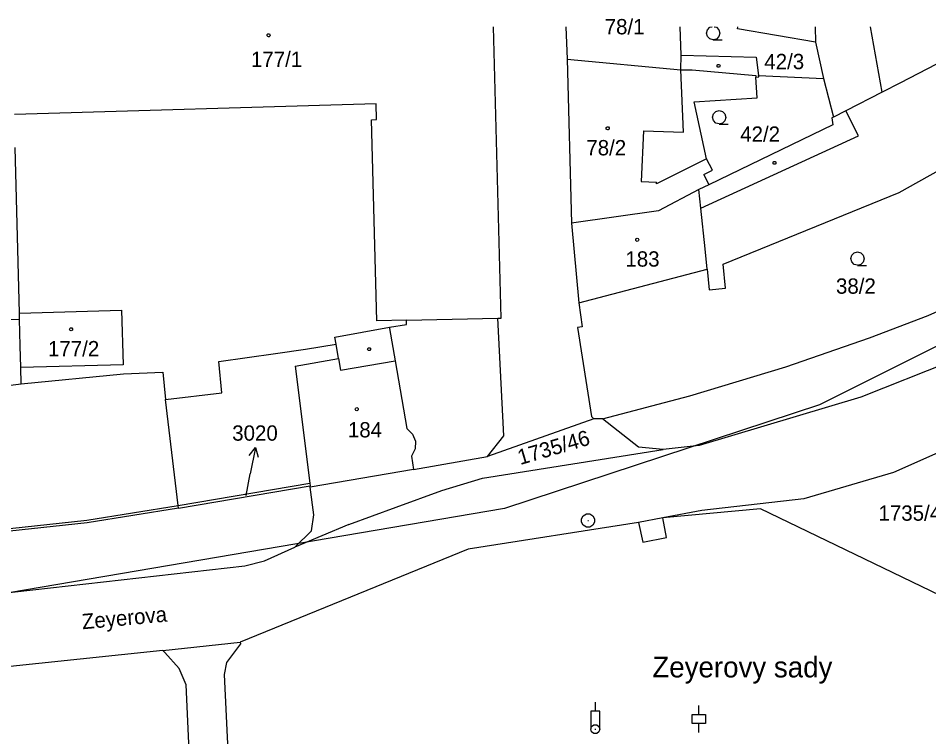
# Model space of a CAD drawing. Extents: x -777309 to -774195, y -1144706 to -1143600.
# Drawn here: x -774798.5 to -774697.4, y -1144278.9 to -1144199.1 of the extents above; entities that cross this region are included whole.
import ezdxf

# ---------------------------------------------------------------- set-up
doc = ezdxf.new("R2010")
doc.units = 0
for name, color, linetype in [('1', 7, 'Continuous'), ('11', 7, 'Continuous'), ('12', 7, 'Continuous'), ('2', 7, 'Continuous'), ('3', 7, 'Continuous'), ('4', 7, 'Continuous'), ('5', 7, 'Continuous'), ('6', 7, 'Continuous'), ('7', 7, 'Continuous'), ('8', 7, 'Continuous')]:
    doc.layers.add(name, color=color, linetype=linetype)

msp = doc.modelspace()

# ---------------------------------------------------------------- linework, layer by layer
at = {"layer": '1'}
for p, q in [((-774744.88, -1144232.39), (-774745.71, -1144200)), ((-774737.67, -1144200), (-774737.55, -1144203.61)), ((-774724.88, -1144203.17), (-774724.98, -1144200)), ((-774718.61, -1144200.24), (-774718.57, -1144200)), ((-774709.96, -1144201.73), (-774718.61, -1144200.24)), ((-774709.99, -1144200), (-774709.96, -1144201.73)), ((-774709.96, -1144201.73), (-774709.07, -1144205.77)), ((-774737.55, -1144203.61), (-774737.05, -1144221.81)), ((-774737.55, -1144203.61), (-774724.92, -1144204.81)), ((-774724.88, -1144203.17), (-774716.53, -1144203.38)), ((-774716.53, -1144203.38), (-774716.27, -1144205.42)), ((-774724.92, -1144204.81), (-774723.65, -1144204.81)), ((-774723.65, -1144204.81), (-774716.59, -1144205.44)), ((-774696.6, -1144204.21), (-774700.52, -1144206.23)), ((-774716.59, -1144205.44), (-774716.58, -1144205.6)), ((-774716.58, -1144205.6), (-774716.26, -1144205.56)), ((-774716.44, -1144207.9), (-774716.58, -1144205.6)), ((-774716.26, -1144205.56), (-774716.27, -1144205.42)), ((-774716.27, -1144205.42), (-774709.07, -1144205.77)), ((-774709.07, -1144205.77), (-774707.96, -1144210.06)), ((-774700.52, -1144206.23), (-774702.57, -1144207.28)), ((-774723.44, -1144208.33), (-774716.44, -1144207.9)), ((-774702.57, -1144207.28), (-774706.6, -1144209.36)), ((-774722.05, -1144214.66), (-774723.44, -1144208.33)), ((-774706.6, -1144209.36), (-774707.96, -1144210.06)), ((-774708.05, -1144210.89), (-774721.82, -1144217.55)), ((-774707.96, -1144210.06), (-774708.15, -1144210.11)), ((-774708.15, -1144210.11), (-774708.05, -1144210.89)), ((-774700.67, -1144218.43), (-774689.32, -1144212.02)), ((-774798.37, -1144231.8), (-774798.85, -1144213.42)), ((-774721.4, -1144215.93), (-774722.05, -1144214.66)), ((-774722.37, -1144216.41), (-774721.4, -1144215.93)), ((-774722.37, -1144216.41), (-774721.82, -1144217.55)), ((-774722.91, -1144218.07), (-774727.41, -1144220.45)), ((-774721.82, -1144217.55), (-774722.91, -1144218.07)), ((-774720.23, -1144226.39), (-774700.67, -1144218.43)), ((-774727.41, -1144220.45), (-774737.05, -1144221.81)), ((-774737.05, -1144221.81), (-774736.23, -1144230.66)), ((-774736.23, -1144230.66), (-774721.99, -1144226.92)), ((-774721.99, -1144226.92), (-774721.75, -1144229.22)), ((-774719.95, -1144229.04), (-774720.23, -1144226.39)), ((-774721.75, -1144229.22), (-774719.95, -1144229.04)), ((-774697.45, -1144232.07), (-774692.97, -1144230.06)), ((-774736.23, -1144230.66), (-774735.86, -1144233.33)), ((-774798.37, -1144231.8), (-774787.02, -1144231.5)), ((-774798.36, -1144232.49), (-774798.37, -1144231.8)), ((-774787.02, -1144231.5), (-774786.86, -1144237.57)), ((-774703.97, -1144234.55), (-774697.45, -1144232.07)), ((-774798.28, -1144235.46), (-774798.36, -1144232.49)), ((-774757.29, -1144233.37), (-774755.38, -1144233.06)), ((-774755.39, -1144232.61), (-774745.25, -1144232.39)), ((-774755.38, -1144233.06), (-774755.39, -1144232.61)), ((-774744.56, -1144245.45), (-774745.25, -1144232.39)), ((-774745.25, -1144232.39), (-774744.88, -1144232.39)), ((-774763.34, -1144234.5), (-774757.29, -1144233.37)), ((-774735.86, -1144233.33), (-774736.39, -1144233.4)), ((-774736.39, -1144233.4), (-774734.85, -1144243.28)), ((-774766.6, -1144235.81), (-774763.21, -1144235.27)), ((-774763.21, -1144235.27), (-774763.34, -1144234.5)), ((-774713.26, -1144237.77), (-774703.97, -1144234.55)), ((-774798.22, -1144237.87), (-774798.28, -1144235.46)), ((-774776.23, -1144237.2), (-774769.93, -1144236.29)), ((-774769.93, -1144236.29), (-774766.6, -1144235.81)), ((-774775.88, -1144240.67), (-774776.23, -1144237.2)), ((-774694.36, -1144236.94), (-774704.94, -1144241.15)), ((-774786.86, -1144237.57), (-774798.22, -1144237.87)), ((-774798.17, -1144239.67), (-774798.22, -1144237.87)), ((-774723.9, -1144240.98), (-774713.26, -1144237.77)), ((-774798.17, -1144239.67), (-774786.83, -1144238.57)), ((-774786.83, -1144238.57), (-774782.45, -1144238.36)), ((-774782.45, -1144238.36), (-774782.14, -1144241.4)), ((-774808.13, -1144240.85), (-774798.17, -1144239.67)), ((-774782.14, -1144241.4), (-774775.88, -1144240.67)), ((-774733.62, -1144243.55), (-774723.9, -1144240.98)), ((-774704.94, -1144241.15), (-774722.87, -1144246.5)), ((-774780.75, -1144253.18), (-774782.14, -1144241.4)), ((-774734.85, -1144243.28), (-774734.58, -1144243.54)), ((-774734.58, -1144243.54), (-774746.39, -1144247.74)), ((-774733.62, -1144243.55), (-774734.58, -1144243.54)), ((-774729.62, -1144246.7), (-774733.62, -1144243.55)), ((-774690.18, -1144244.53), (-774701.28, -1144249.52)), ((-774746.39, -1144247.74), (-774744.56, -1144245.45)), ((-774746.93, -1144250.16), (-774726.89, -1144246.95)), ((-774726.89, -1144246.95), (-774729.62, -1144246.7)), ((-774722.87, -1144246.5), (-774726.89, -1144246.95)), ((-774754.59, -1144249.19), (-774746.39, -1144247.74)), ((-774754.59, -1144249.19), (-774766.07, -1144251.14)), ((-774751.47, -1144251.53), (-774746.93, -1144250.16)), ((-774701.28, -1144249.52), (-774711.26, -1144252.45)), ((-774780.75, -1144253.18), (-774766.11, -1144250.71)), ((-774780.72, -1144253.48), (-774766.07, -1144251.01)), ((-774766.11, -1144250.71), (-774766.07, -1144251.01)), ((-774766.07, -1144251.14), (-774766.07, -1144251.01)), ((-774765.68, -1144254.21), (-774766.07, -1144251.14)), ((-774756.55, -1144253.36), (-774751.47, -1144251.53)), ((-774711.26, -1144252.45), (-774722.58, -1144253.73)), ((-774790.9, -1144254.82), (-774780.75, -1144253.18)), ((-774780.72, -1144253.48), (-774790.85, -1144255.12)), ((-774780.72, -1144253.48), (-774780.75, -1144253.18)), ((-774761.79, -1144255.3), (-774756.55, -1144253.36)), ((-774765.94, -1144256.01), (-774765.68, -1144254.21)), ((-774716.05, -1144253.53), (-774726.9, -1144254.54)), ((-774722.58, -1144253.73), (-774726.9, -1144254.54)), ((-774668.54, -1144276.54), (-774716.05, -1144253.53)), ((-774809.2, -1144256.75), (-774790.9, -1144254.82)), ((-774790.85, -1144255.12), (-774809.17, -1144257.05)), ((-774761.79, -1144255.3), (-774767.79, -1144257.79)), ((-774729.6, -1144255.07), (-774748.54, -1144258.04)), ((-774726.9, -1144254.54), (-774729.6, -1144255.07)), ((-774767.79, -1144257.79), (-774765.94, -1144256.01)), ((-774748.54, -1144258.04), (-774773.87, -1144268.37)), ((-774771.17, -1144259.33), (-774767.79, -1144257.79)), ((-774773.33, -1144259.89), (-774771.17, -1144259.33)), ((-774818.72, -1144265.01), (-774773.33, -1144259.89)), ((-774782.45, -1144269.27), (-774773.87, -1144268.37)), ((-774773.83, -1144268.54), (-774775.39, -1144270.6)), ((-774773.87, -1144268.37), (-774773.83, -1144268.54)), ((-774782.45, -1144269.27), (-774818.84, -1144273.07)), ((-774775.39, -1144270.6), (-774775.64, -1144271.95)), ((-774775.64, -1144271.95), (-774774.8, -1144288.74))]:
    msp.add_line(p, q, dxfattribs=at)
at = {"layer": '11'}
msp.add_lwpolyline([(-774645.08, -1144200), (-774645.5, -1144200.5), (-774681.5, -1144228), (-774709.5, -1144242), (-774744.5, -1144253.5), (-774812, -1144265), (-774860.5, -1144263), (-774969.04, -1144252.1), (-774980.31, -1144239.8), (-774996.3, -1144228.96), (-775000, -1144226.45), (-775000, -1144224.76), (-775020.31, -1144224.68)], dxfattribs=at)
at = {"layer": '12'}
for p, q in [((-774744.88, -1144232.39), (-774745.71, -1144200)), ((-774737.67, -1144200), (-774737.55, -1144203.61)), ((-774724.88, -1144203.17), (-774724.98, -1144200)), ((-774737.55, -1144203.61), (-774724.92, -1144204.81)), ((-774737.55, -1144203.61), (-774737.05, -1144221.81)), ((-774737.55, -1144203.61), (-774724.92, -1144204.81)), ((-774724.92, -1144204.81), (-774724.88, -1144203.17)), ((-774724.62, -1144211.72), (-774724.92, -1144204.81)), ((-774758.75, -1144208.58), (-774798.94, -1144209.74)), ((-774758.7, -1144210.32), (-774758.75, -1144208.58)), ((-774759.27, -1144210.33), (-774758.7, -1144210.32)), ((-774758.67, -1144232.68), (-774759.27, -1144210.33)), ((-774729.06, -1144211.58), (-774729.33, -1144217.2)), ((-774729.06, -1144211.58), (-774724.62, -1144211.72)), ((-774722.05, -1144214.66), (-774727.6, -1144217.47)), ((-774721.4, -1144215.93), (-774722.05, -1144214.66)), ((-774722.37, -1144216.41), (-774721.4, -1144215.93)), ((-774722.37, -1144216.41), (-774721.82, -1144217.55)), ((-774729.33, -1144217.2), (-774727.61, -1144217.28)), ((-774727.6, -1144217.47), (-774727.61, -1144217.28)), ((-774722.91, -1144218.07), (-774727.41, -1144220.45)), ((-774722.91, -1144218.07), (-774727.41, -1144220.45)), ((-774721.82, -1144217.55), (-774722.91, -1144218.07)), ((-774722.69, -1144220.17), (-774722.91, -1144218.07)), ((-774727.41, -1144220.45), (-774737.05, -1144221.81)), ((-774727.41, -1144220.45), (-774737.05, -1144221.81)), ((-774722.23, -1144224.67), (-774722.69, -1144220.17)), ((-774737.05, -1144221.81), (-774736.23, -1144230.66)), ((-774721.99, -1144226.92), (-774722.23, -1144224.67)), ((-774736.23, -1144230.66), (-774721.99, -1144226.92)), ((-774798.37, -1144231.8), (-774787.02, -1144231.5)), ((-774798.36, -1144232.49), (-774798.37, -1144231.8)), ((-774787.02, -1144231.5), (-774786.86, -1144237.57)), ((-774798.28, -1144235.46), (-774798.36, -1144232.49)), ((-774755.39, -1144232.61), (-774758.67, -1144232.68)), ((-774755.39, -1144232.61), (-774745.25, -1144232.39)), ((-774745.25, -1144232.39), (-774744.88, -1144232.39)), ((-774798.22, -1144237.87), (-774798.28, -1144235.46)), ((-774767.74, -1144237.72), (-774762.93, -1144236.84)), ((-774762.93, -1144236.84), (-774762.7, -1144238.13)), ((-774762.7, -1144238.13), (-774756.65, -1144237.1)), ((-774756.65, -1144237.1), (-774755.36, -1144244.64)), ((-774786.86, -1144237.57), (-774798.22, -1144237.87)), ((-774767.74, -1144237.72), (-774766.11, -1144250.71)), ((-774755.36, -1144244.64), (-774754.7, -1144245.25)), ((-774754.7, -1144245.25), (-774754.38, -1144246.04)), ((-774754.38, -1144246.04), (-774754.41, -1144246.88)), ((-774754.41, -1144246.88), (-774754.84, -1144247.69)), ((-774754.84, -1144247.69), (-774754.59, -1144249.19)), ((-774754.59, -1144249.19), (-774766.07, -1144251.14)), ((-774766.11, -1144250.71), (-774766.07, -1144251.01)), ((-774766.07, -1144251.14), (-774766.07, -1144251.01))]:
    msp.add_line(p, q, dxfattribs=at)
at = {"layer": '3'}
msp.add_line((-774722.91, -1144276.38), (-774722.91, -1144275.38), dxfattribs=at)
for points in [[(-774721.31, -1144201.45), (-774721.69, -1144201.35), (-774721.96, -1144201.08), (-774722.06, -1144200.71), (-774721.96, -1144200.34), (-774721.69, -1144200.07), (-774721.43, -1144200)], [(-774721.21, -1144200), (-774720.95, -1144200.07), (-774720.68, -1144200.34), (-774720.58, -1144200.72), (-774720.68, -1144201.1), (-774720.95, -1144201.37), (-774721.33, -1144201.47), (-774720.33, -1144201.47)], [(-774720.64, -1144210.8), (-774721.02, -1144210.7), (-774721.29, -1144210.43), (-774721.39, -1144210.06), (-774721.29, -1144209.69), (-774721.02, -1144209.42), (-774720.65, -1144209.32), (-774720.28, -1144209.42), (-774720.01, -1144209.69), (-774719.91, -1144210.07), (-774720.01, -1144210.45), (-774720.28, -1144210.72), (-774720.66, -1144210.82), (-774719.66, -1144210.82)], [(-774705.28, -1144226.5), (-774705.66, -1144226.4), (-774705.93, -1144226.13), (-774706.03, -1144225.76), (-774705.93, -1144225.39), (-774705.66, -1144225.12), (-774705.29, -1144225.02), (-774704.92, -1144225.12), (-774704.65, -1144225.39), (-774704.55, -1144225.77), (-774704.65, -1144226.15), (-774704.92, -1144226.42), (-774705.3, -1144226.52), (-774704.3, -1144226.52)], [(-774722.91, -1144278.38), (-774722.91, -1144277.38), (-774723.66, -1144277.38), (-774723.66, -1144276.38), (-774722.91, -1144276.38), (-774722.16, -1144276.38), (-774722.16, -1144277.38), (-774722.91, -1144277.38)]]:
    msp.add_lwpolyline(points, dxfattribs=at)
at = {"layer": '4'}
for p, q in [((-774702.57, -1144207.28), (-774703.84, -1144200)), ((-774724.92, -1144204.81), (-774724.88, -1144203.17)), ((-774724.62, -1144211.72), (-774724.92, -1144204.81)), ((-774758.75, -1144208.58), (-774798.94, -1144209.74)), ((-774758.7, -1144210.32), (-774758.75, -1144208.58)), ((-774705.17, -1144212.14), (-774706.6, -1144209.36)), ((-774759.27, -1144210.33), (-774758.7, -1144210.32)), ((-774758.67, -1144232.68), (-774759.27, -1144210.33)), ((-774729.06, -1144211.58), (-774729.33, -1144217.2)), ((-774729.06, -1144211.58), (-774724.62, -1144211.72)), ((-774722.69, -1144220.17), (-774705.17, -1144212.14)), ((-774722.05, -1144214.66), (-774727.6, -1144217.47)), ((-774729.33, -1144217.2), (-774727.61, -1144217.28)), ((-774727.6, -1144217.47), (-774727.61, -1144217.28)), ((-774722.69, -1144220.17), (-774722.91, -1144218.07)), ((-774722.23, -1144224.67), (-774722.69, -1144220.17)), ((-774721.99, -1144226.92), (-774722.23, -1144224.67)), ((-774803.88, -1144232.63), (-774798.36, -1144232.49)), ((-774755.39, -1144232.61), (-774758.67, -1144232.68)), ((-774757.29, -1144233.37), (-774757.26, -1144233.52)), ((-774757.26, -1144233.52), (-774756.65, -1144237.1)), ((-774762.93, -1144236.84), (-774763.21, -1144235.27)), ((-774767.74, -1144237.72), (-774762.93, -1144236.84)), ((-774762.93, -1144236.84), (-774762.7, -1144238.13)), ((-774762.7, -1144238.13), (-774756.65, -1144237.1)), ((-774756.65, -1144237.1), (-774755.36, -1144244.64)), ((-774767.74, -1144237.72), (-774766.11, -1144250.71)), ((-774755.36, -1144244.64), (-774754.7, -1144245.25)), ((-774754.7, -1144245.25), (-774754.38, -1144246.04)), ((-774754.38, -1144246.04), (-774754.41, -1144246.88)), ((-774754.41, -1144246.88), (-774754.84, -1144247.69)), ((-774754.84, -1144247.69), (-774754.59, -1144249.19)), ((-774729.6, -1144255.07), (-774729.15, -1144257.25)), ((-774726.49, -1144256.74), (-774726.9, -1144254.54)), ((-774729.15, -1144257.25), (-774726.49, -1144256.74)), ((-774782.23, -1144269.51), (-774782.45, -1144269.27)), ((-774780.65, -1144271.29), (-774782.23, -1144269.51)), ((-774779.87, -1144273.1), (-774780.65, -1144271.29)), ((-774778.76, -1144295.44), (-774779.87, -1144273.1))]:
    msp.add_line(p, q, dxfattribs=at)
at = {"layer": '5'}
for points in [[(-774770.7, -1144200.78), (-774770.6, -1144200.8), (-774770.55, -1144200.89), (-774770.53, -1144200.95), (-774770.55, -1144201.04), (-774770.63, -1144201.11), (-774770.7, -1144201.12), (-774770.79, -1144201.09), (-774770.85, -1144201.03), (-774770.87, -1144200.95), (-774770.85, -1144200.86), (-774770.77, -1144200.79)], [(-774720.63, -1144204.2), (-774720.54, -1144204.35), (-774720.63, -1144204.5), (-774720.81, -1144204.5), (-774720.9, -1144204.35), (-774720.81, -1144204.2)], [(-774733.04, -1144211.12), (-774732.94, -1144211.14), (-774732.89, -1144211.23), (-774732.87, -1144211.29), (-774732.89, -1144211.38), (-774732.97, -1144211.45), (-774733.04, -1144211.46), (-774733.13, -1144211.43), (-774733.19, -1144211.37), (-774733.21, -1144211.29), (-774733.19, -1144211.2), (-774733.11, -1144211.13)], [(-774714.42, -1144214.98), (-774714.33, -1144215.13), (-774714.42, -1144215.28), (-774714.6, -1144215.28), (-774714.69, -1144215.13), (-774714.6, -1144214.98)], [(-774729.76, -1144223.5), (-774729.66, -1144223.52), (-774729.61, -1144223.61), (-774729.59, -1144223.67), (-774729.61, -1144223.76), (-774729.69, -1144223.83), (-774729.76, -1144223.84), (-774729.85, -1144223.81), (-774729.91, -1144223.75), (-774729.93, -1144223.67), (-774729.91, -1144223.58), (-774729.83, -1144223.51)], [(-774792.64, -1144233.43), (-774792.54, -1144233.45), (-774792.49, -1144233.54), (-774792.47, -1144233.6), (-774792.49, -1144233.69), (-774792.57, -1144233.76), (-774792.64, -1144233.77), (-774792.73, -1144233.74), (-774792.79, -1144233.68), (-774792.81, -1144233.6), (-774792.79, -1144233.51), (-774792.71, -1144233.44)], [(-774759.45, -1144235.67), (-774759.36, -1144235.82), (-774759.45, -1144235.97), (-774759.63, -1144235.97), (-774759.72, -1144235.82), (-774759.63, -1144235.67)], [(-774760.91, -1144242.31), (-774760.81, -1144242.33), (-774760.76, -1144242.42), (-774760.74, -1144242.48), (-774760.76, -1144242.57), (-774760.84, -1144242.64), (-774760.91, -1144242.65), (-774761, -1144242.62), (-774761.06, -1144242.56), (-774761.08, -1144242.48), (-774761.06, -1144242.39), (-774760.98, -1144242.32)]]:
    msp.add_lwpolyline(points, close=True, dxfattribs=at)
at = {"layer": '6'}
for p, q in [((-774734.41, -1144276.02), (-774734.41, -1144275.02)), ((-774734.46, -1144278.02), (-774734.36, -1144278.02))]:
    msp.add_line(p, q, dxfattribs=at)
for points in [[(-774733.91, -1144278.02), (-774734.01, -1144278.31), (-774734.26, -1144278.49), (-774734.57, -1144278.49), (-774734.82, -1144278.31), (-774734.92, -1144278.02), (-774734.82, -1144277.73), (-774734.57, -1144277.55), (-774734.26, -1144277.55), (-774734.01, -1144277.73), (-774733.91, -1144278.02), (-774733.91, -1144276.75), (-774733.91, -1144276.02), (-774734.41, -1144276.02), (-774734.91, -1144276.02), (-774734.91, -1144277.29), (-774734.91, -1144278.02)], [(-774734.46, -1144278.02), (-774734.41, -1144278.02), (-774734.36, -1144278.02)]]:
    msp.add_lwpolyline(points, dxfattribs=at)
at = {"layer": '7'}
for p in [(-774772.17, -1144246.72), (-774773.19, -1144252.06)]:
    msp.add_line(p, (-774772.73, -1144249.67), dxfattribs=at)
msp.add_lwpolyline([(-774772.85, -1144247.61), (-774772.17, -1144246.72), (-774771.87, -1144247.8)], dxfattribs=at)
at = {"layer": '8'}
msp.add_line((-774735.26, -1144254.84), (-774735.16, -1144254.84), dxfattribs=at)
msp.add_lwpolyline([(-774735.02, -1144254.12), (-774734.68, -1144254.31), (-774734.49, -1144254.65), (-774734.49, -1144255.04), (-774734.68, -1144255.38), (-774735.02, -1144255.57), (-774735.41, -1144255.57), (-774735.75, -1144255.38), (-774735.94, -1144255.04), (-774735.94, -1144254.65), (-774735.75, -1144254.31), (-774735.41, -1144254.12)], close=True, dxfattribs=at)

# ---------------------------------------------------------------- texts
at = {"layer": '2'}
for s, height, p in [('78/1', 1.7, (-774733.37, -1144200.85)), ('177/1', 1.7, (-774772.66, -1144204.47)), ('42/3', 1.7, (-774715.64, -1144204.72)), ('42/2', 1.7, (-774718.32, -1144212.78)), ('78/2', 1.7, (-774735.41, -1144214.29)), ('183', 1.7, (-774731.07, -1144226.65)), ('38/2', 1.7, (-774707.68, -1144229.66)), ('177/2', 1.7, (-774795.2, -1144236.61)), ('184', 1.7, (-774761.89, -1144245.62)), ('3020', 0.1, (-774773.36, -1144252.06)), ('1735/45', 1.7, (-774702.96, -1144254.87))]:
    msp.add_text(s, height=height, dxfattribs=at).set_placement(p)
msp.add_text('1735/46', height=1.7, rotation=16.272, dxfattribs=at).set_placement((-774742.76, -1144248.69))
at = {"layer": '7'}
for s, height, p in [('3020', 1.7, (-774774.74, -1144245.98)), ('Zeyerovy sady', 2.3, (-774728.08, -1144272.27))]:
    msp.add_text(s, height=height, dxfattribs=at).set_placement(p)
msp.add_text('Zeyerova', height=1.7, rotation=5.2139, dxfattribs=at).set_placement((-774791.36, -1144266.93))

doc.saveas('drawing.dxf')
